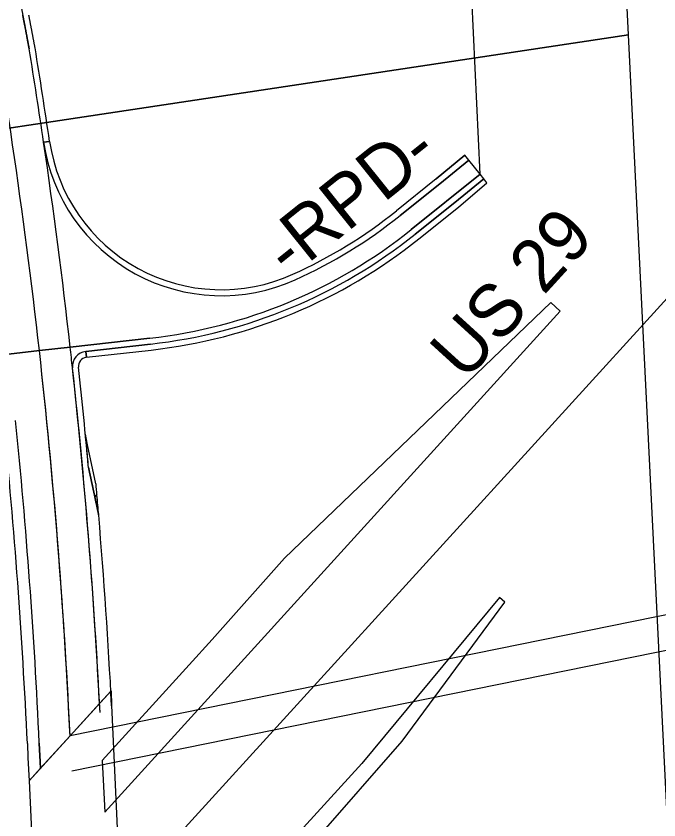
# Model space of a CAD drawing. Extents: x 1805231 to 1809482, y 908883 to 918297.
# Drawn here: x 1807848 to 1808278, y 914790 to 915327 of the extents above; entities that cross this region are included whole.
import ezdxf

# ---------------------------------------------------------------- set-up
doc = ezdxf.new("R2010")
doc.units = 0
for name, color, linetype in [('Old_Level_50', 7, 'Continuous'), ('Prop DSN Text', 7, 'Continuous'), ('Prop Horizontal Alignment', 7, 'Continuous'), ('Prop Horizontal Alignment Station Label', 7, 'Continuous'), ('Prop Shade Medium', 7, 'Continuous')]:
    doc.layers.add(name, color=color, linetype=linetype)

msp = doc.modelspace()

# ---------------------------------------------------------------- linework, layer by layer
at = {"layer": 'Old_Level_50'}
msp.add_lwpolyline([(1807870.06, 914531.76), (1807924.83, 914591.86), (1807911.63, 914876.72), (1807856.86, 914816.62)], close=True, dxfattribs=at)
at = {"layer": 'Prop DSN Text'}
for p, q in [((1807852.79, 915327.36), (1807852.79, 915327.36)), ((1807852.91, 915326.77), (1807852.79, 915327.36)), ((1807856.87, 915305.75), (1807856.77, 915306.3)), ((1807856.93, 915305.41), (1807856.87, 915305.75)), ((1807870.56, 915243.69), (1807866.6, 915243.11)), ((1807870.56, 915243.69), (1807866.6, 915243.11)), ((1807866.6, 915243.11), (1807870.56, 915243.69)), ((1808128.8, 915218.55), (1808148.08, 915234.46)), ((1808148.08, 915234.46), (1808128.8, 915218.55)), ((1808150.74, 915231.15), (1808148.08, 915234.46)), ((1808131.3, 915215.42), (1808150.74, 915231.15)), ((1808150.74, 915231.15), (1808131.3, 915215.42)), ((1808158.31, 915221.69), (1808150.74, 915231.15)), ((1808128.8, 915218.55), (1808102.25, 915197.27)), ((1808112.25, 915184.78), (1808158.31, 915221.69)), ((1808158.31, 915221.69), (1808112.25, 915184.78)), ((1808160.71, 915218.7), (1808141.31, 915202.94)), ((1808141.31, 915202.94), (1808160.71, 915218.7)), ((1808160.71, 915218.7), (1808158.31, 915221.69)), ((1808162.81, 915216.08), (1808160.71, 915218.7)), ((1808104.75, 915194.15), (1808131.3, 915215.42)), ((1808131.3, 915215.42), (1808104.75, 915194.15)), ((1808143.81, 915199.82), (1808162.81, 915216.08)), ((1808141.31, 915202.94), (1808114.75, 915181.66)), ((1808114.75, 915181.66), (1808141.31, 915202.94)), ((1808117.25, 915178.54), (1808143.81, 915199.82)), ((1808205.39, 915135.94), (1808027.54, 914965.21)), ((1808211.73, 915130.28), (1808205.39, 915135.94)), ((1807907.38, 914795.62), (1808211.73, 915130.28)), ((1807884.35, 915106.27), (1807937.6, 915112.25)), ((1807937.6, 915112.25), (1807884.35, 915106.27)), ((1807863.73, 915103.95), (1807884.35, 915106.27)), ((1807884.35, 915106.27), (1807863.73, 915103.95)), ((1807938.05, 915108.27), (1807894.71, 915103.41)), ((1807894.71, 915103.41), (1807938.05, 915108.27)), ((1807843.11, 915101.64), (1807863.73, 915103.95)), ((1807863.73, 915103.95), (1807843.11, 915101.64)), ((1807895.16, 915099.43), (1807894.71, 915103.41)), ((1807894.71, 915103.41), (1807895.16, 915099.43)), ((1807895.16, 915099.43), (1807894.71, 915103.41)), ((1807895.16, 915099.43), (1807938.49, 915104.3)), ((1808931.8, 915059), (1807884.24, 914846.67)), ((1807896.01, 915040.98), (1807894.47, 915048.14)), ((1807896.01, 915040.98), (1807895.19, 915040.72)), ((1807895.19, 915040.72), (1807896.01, 915040.98)), ((1807901.58, 915014.95), (1807896.01, 915040.98)), ((1808787.62, 915005.99), (1807885.34, 914823.11)), ((1808027.54, 914965.21), (1807979.3, 914910.89)), ((1808171.26, 914939.03), (1808079.12, 914828.16)), ((1808174.73, 914935.87), (1808171.26, 914939.03)), ((1807979.3, 914910.89), (1807963.89, 914893.98)), ((1807963.89, 914893.98), (1807905.78, 914830.23)), ((1807884.24, 914846.67), (1807903.94, 914868.28)), ((1807912.04, 914866.67), (1807912.02, 914867.05)), ((1807855.71, 914841.42), (1807856.15, 914831.97)), ((1807864.48, 914824.99), (1807863.7, 914841.79)), ((1807863.7, 914841.79), (1807864.48, 914824.99)), ((1807905.78, 914830.23), (1807907.38, 914795.62)), ((1808079.12, 914828.16), (1807914.26, 914647.28))]:
    msp.add_line(p, q, dxfattribs=at)
for points in [[(1807900.77, 915006.39), (1807901.83, 915007.21), (1807902.24, 915007.53)], [(1807902.24, 915007.53), (1807901.83, 915007.21), (1807900.77, 915006.39)], [(1807984.27, 914696.64), (1808048.82, 914777.64), (1808106.13, 914843.12), (1808174.73, 914935.87)], [(1807904.26, 914862.18), (1807903.94, 914868.28), (1807911.63, 914876.72), (1807912.04, 914866.67)], [(1807864.48, 914824.99), (1807884.24, 914846.67), (1807884.11, 914849.53)], [(1807856.15, 914831.97), (1807856.86, 914816.62), (1807864.48, 914824.99)]]:
    msp.add_lwpolyline(points, dxfattribs=at)
for centre, radius, start, end in [((1803888.72, 914657.58), 4000, 6.4071, 10.37717), ((1803888.72, 914657.58), 4000, 6.4071, 10.37717), ((1803888.72, 914657.58), 4020.75, 8.37352, 9.27189), ((1803888.72, 914657.58), 4020.75, 8.37352, 9.27189), ((1803888.72, 914657.58), 4024.75, 8.37352, 9.27189), ((1807985.32, 915260.58), 120, 188.3735, 294.3215), ((1807985.32, 915260.58), 120, 188.3735, 294.3215), ((1803888.72, 914657.58), 4020.75, 6.4071, 8.37352), ((1803888.72, 914657.58), 4020.75, 6.4071, 8.37352), ((1807985.32, 915260.58), 116, 188.3735, 294.3215), ((1807899.66, 915450.12), 324, 294.3215, 308.7021), ((1807899.66, 915450.12), 328, 294.3215, 308.7021), ((1807899.66, 915450.12), 328, 294.3215, 308.7021), ((1807899.66, 915450.12), 340, 276.4071, 308.7021), ((1807899.66, 915450.12), 340, 276.4071, 308.7021), ((1807899.66, 915450.12), 344, 276.4071, 308.7021), ((1807899.66, 915450.12), 344, 276.4071, 308.7021), ((1807899.66, 915450.12), 348, 276.4071, 308.7021), ((1803888.72, 914657.58), 4020.75, 6.20809, 6.4071), ((1803888.72, 914657.58), 4020.75, 6.20809, 6.4071), ((1803888.72, 914657.58), 4000, 2.75044, 6.4071), ((1803844.06, 914654.02), 4044.77, 2.72997, 6.38663), ((1807895.83, 915093.47), 10, 96.4071, 186.2081), ((1807895.83, 915093.47), 10, 96.4071, 186.2081), ((1807895.83, 915093.47), 6, 96.4071, 186.2081), ((1803888.72, 914657.58), 4020.75, 2.91678, 6.20809), ((1803994.75, 914666.13), 3914.41, 2.96032, 6.25163), ((1803888.72, 914657.58), 4024.75, 5.24815, 6.20809), ((1803888.72, 914657.58), 3979.25, 2.65322, 5.76578), ((1803888.72, 914657.58), 3979.25, 2.65322, 5.76578), ((1803888.72, 914657.58), 3971.25, 2.65322, 5.76578), ((1803888.72, 914657.58), 4024.75, 5.46254, 5.56861), ((1803888.72, 914657.58), 4024.75, 5.24815, 5.46254), ((1803888.72, 914657.58), 4028.75, 4.98316, 5.08905), ((1803888.72, 914657.58), 4028.75, 4.78978, 4.98316), ((1803888.72, 914657.58), 4028.75, 2.98039, 4.78978)]:
    msp.add_arc(centre, radius, start, end, dxfattribs=at)
for points in [[(1807848.53, 915349.29), (1807848.59, 915348.99), (1807848.77, 915348.1), (1807848.94, 915347.22), (1807849.12, 915346.33), (1807849.29, 915345.44), (1807849.47, 915344.55), (1807849.64, 915343.66), (1807849.81, 915342.77), (1807849.99, 915341.88), (1807850.16, 915340.99), (1807850.33, 915340.11), (1807850.51, 915339.22), (1807850.68, 915338.33), (1807850.85, 915337.44), (1807851.02, 915336.55), (1807851.2, 915335.66), (1807851.37, 915334.77), (1807851.54, 915333.88), (1807851.71, 915332.99), (1807851.88, 915332.1), (1807852.05, 915331.21), (1807852.23, 915330.32), (1807852.4, 915329.44), (1807852.57, 915328.55), (1807852.74, 915327.66), (1807852.79, 915327.36)], [(1807852.79, 915327.36), (1807852.91, 915326.77), (1807853.08, 915325.88), (1807853.25, 915324.99), (1807853.42, 915324.1), (1807853.59, 915323.21), (1807853.76, 915322.32), (1807853.93, 915321.43), (1807854.09, 915320.54), (1807854.26, 915319.65), (1807854.43, 915318.76), (1807854.6, 915317.87), (1807854.77, 915316.98), (1807854.94, 915316.09), (1807855.1, 915315.2), (1807855.27, 915314.31), (1807855.44, 915313.42), (1807855.6, 915312.53), (1807855.77, 915311.64), (1807855.94, 915310.75), (1807856.1, 915309.86), (1807856.27, 915308.97), (1807856.44, 915308.08), (1807856.6, 915307.19), (1807856.77, 915306.3), (1807856.93, 915305.41)], [(1807860.88, 915306.05), (1807860.7, 915307.03), (1807860.54, 915307.92), (1807860.37, 915308.81), (1807860.2, 915309.7), (1807860.04, 915310.59), (1807859.87, 915311.48), (1807859.7, 915312.37), (1807859.54, 915313.27), (1807859.37, 915314.16), (1807859.2, 915315.05), (1807859.03, 915315.94), (1807858.87, 915316.83), (1807858.7, 915317.72), (1807858.53, 915318.61), (1807858.36, 915319.5), (1807858.19, 915320.39), (1807858.02, 915321.28), (1807857.85, 915322.17), (1807857.69, 915323.07), (1807857.52, 915323.96), (1807857.35, 915324.85), (1807857.18, 915325.74), (1807857.01, 915326.63), (1807856.84, 915327.52), (1807856.73, 915328.05)], [(1807853.89, 915321.61), (1807853.76, 915322.32), (1807853.62, 915323.04)], [(1807854.78, 915316.89), (1807854.77, 915316.98), (1807854.6, 915317.87), (1807854.43, 915318.76), (1807854.26, 915319.65), (1807854.09, 915320.54), (1807853.93, 915321.43), (1807853.89, 915321.61)], [(1807855.34, 915313.93), (1807855.27, 915314.31), (1807855.1, 915315.2), (1807854.94, 915316.09), (1807854.78, 915316.89)], [(1807898.89, 915015.15), (1807898.83, 915015.44), (1807898.73, 915015.87), (1807898.64, 915016.3), (1807898.55, 915016.73), (1807898.46, 915017.16), (1807898.36, 915017.58), (1807898.27, 915018.01), (1807898.18, 915018.44), (1807898.09, 915018.87), (1807897.99, 915019.3), (1807897.9, 915019.73), (1807897.81, 915020.16), (1807897.71, 915020.58), (1807897.62, 915021.01), (1807897.53, 915021.44), (1807897.43, 915021.87), (1807897.34, 915022.3), (1807897.25, 915022.73), (1807897.15, 915023.16), (1807897.06, 915023.58), (1807896.97, 915024.01), (1807896.87, 915024.44), (1807896.78, 915024.87), (1807896.59, 915025.73)], [(1807896.59, 915025.73), (1807896.78, 915024.87), (1807896.87, 915024.44), (1807896.97, 915024.01), (1807897.06, 915023.58), (1807897.15, 915023.16), (1807897.25, 915022.73), (1807897.34, 915022.3), (1807897.43, 915021.87), (1807897.53, 915021.44), (1807897.62, 915021.01), (1807897.71, 915020.58), (1807897.81, 915020.16), (1807897.9, 915019.73), (1807897.99, 915019.3), (1807898.09, 915018.87), (1807898.18, 915018.44), (1807898.27, 915018.01), (1807898.36, 915017.58), (1807898.46, 915017.16), (1807898.55, 915016.73), (1807898.64, 915016.3), (1807898.73, 915015.87), (1807898.83, 915015.44), (1807898.89, 915015.15)], [(1807901.16, 915004.57), (1807901.13, 915004.72), (1807901.03, 915005.15), (1807900.94, 915005.58), (1807900.85, 915006), (1807900.76, 915006.43), (1807900.67, 915006.86), (1807900.58, 915007.29), (1807900.49, 915007.72), (1807900.39, 915008.15), (1807900.3, 915008.58), (1807900.21, 915009.01), (1807900.12, 915009.44), (1807900.03, 915009.87), (1807899.93, 915010.29), (1807899.84, 915010.72), (1807899.75, 915011.15), (1807899.66, 915011.58), (1807899.57, 915012.01), (1807899.47, 915012.44), (1807899.38, 915012.87), (1807899.29, 915013.3), (1807899.2, 915013.73), (1807899.1, 915014.15), (1807899.01, 915014.58), (1807898.92, 915015.01), (1807898.89, 915015.15)], [(1807898.89, 915015.15), (1807898.92, 915015.01), (1807899.01, 915014.58), (1807899.1, 915014.15), (1807899.2, 915013.73), (1807899.29, 915013.3), (1807899.38, 915012.87), (1807899.47, 915012.44), (1807899.57, 915012.01), (1807899.66, 915011.58), (1807899.75, 915011.15), (1807899.84, 915010.72), (1807899.93, 915010.29), (1807900.03, 915009.87), (1807900.12, 915009.44), (1807900.21, 915009.01), (1807900.3, 915008.58), (1807900.39, 915008.15), (1807900.49, 915007.72), (1807900.58, 915007.29), (1807900.67, 915006.86), (1807900.76, 915006.43), (1807900.77, 915006.39)], [(1807900.77, 915006.39), (1807900.85, 915006), (1807900.94, 915005.58), (1807901.03, 915005.15), (1807901.13, 915004.72), (1807901.16, 915004.57)], [(1807903.4, 914993.98), (1807903.31, 914994.41), (1807903.22, 914994.84), (1807903.13, 914995.27), (1807903.03, 914995.7), (1807902.94, 914996.13), (1807902.85, 914996.56), (1807902.76, 914996.99), (1807902.67, 914997.42), (1807902.58, 914997.85), (1807902.49, 914998.28), (1807902.4, 914998.71), (1807902.31, 914999.14), (1807902.22, 914999.57), (1807902.13, 915000), (1807902.04, 915000.43), (1807901.95, 915000.86), (1807901.86, 915001.28), (1807901.76, 915001.71), (1807901.67, 915002.14), (1807901.58, 915002.57), (1807901.49, 915003), (1807901.4, 915003.43), (1807901.31, 915003.86), (1807901.22, 915004.29), (1807901.16, 915004.57)], [(1807901.16, 915004.57), (1807901.22, 915004.29), (1807901.31, 915003.86), (1807901.4, 915003.43), (1807901.49, 915003), (1807901.58, 915002.57), (1807901.67, 915002.14), (1807901.76, 915001.71), (1807901.86, 915001.28), (1807901.95, 915000.86), (1807902.04, 915000.43), (1807902.13, 915000), (1807902.22, 914999.57), (1807902.31, 914999.14), (1807902.4, 914998.71), (1807902.49, 914998.28), (1807902.58, 914997.85), (1807902.67, 914997.42), (1807902.76, 914996.99), (1807902.85, 914996.56), (1807902.94, 914996.13), (1807903.03, 914995.7), (1807903.13, 914995.27), (1807903.22, 914994.84), (1807903.31, 914994.41), (1807903.4, 914993.98)]]:
    msp.add_spline(points, degree=3, dxfattribs=at)
for points in [[(1807852.79, 915327.36), (1807852.78, 915327.46), (1807852.76, 915327.56), (1807852.74, 915327.66), (1807852.71, 915327.78), (1807852.69, 915327.91), (1807852.67, 915328.03)], [(1807853.08, 915325.88), (1807853.02, 915326.17), (1807852.96, 915326.47), (1807852.91, 915326.77), (1807852.91, 915326.77), (1807852.91, 915326.77), (1807852.91, 915326.77)], [(1807853.3, 915324.73), (1807853.28, 915324.82), (1807853.26, 915324.9), (1807853.25, 915324.99), (1807853.19, 915325.28), (1807853.13, 915325.58), (1807853.08, 915325.88), (1807853.08, 915325.88), (1807853.08, 915325.88), (1807853.08, 915325.88)], [(1807853.62, 915323.04), (1807853.61, 915323.09), (1807853.6, 915323.15), (1807853.59, 915323.21), (1807853.53, 915323.5), (1807853.47, 915323.8), (1807853.42, 915324.1), (1807853.38, 915324.31), (1807853.34, 915324.52), (1807853.3, 915324.73)], [(1807856.16, 915309.57), (1807856.14, 915309.66), (1807856.12, 915309.76), (1807856.1, 915309.86), (1807856.05, 915310.15), (1807855.99, 915310.45), (1807855.94, 915310.75), (1807855.88, 915311.04), (1807855.83, 915311.34), (1807855.77, 915311.64), (1807855.72, 915311.94), (1807855.66, 915312.23), (1807855.6, 915312.53), (1807855.55, 915312.83), (1807855.49, 915313.12), (1807855.44, 915313.42), (1807855.41, 915313.59), (1807855.37, 915313.76), (1807855.34, 915313.93)], [(1807856.77, 915306.3), (1807856.77, 915306.3), (1807856.77, 915306.3), (1807856.77, 915306.3), (1807856.71, 915306.59), (1807856.66, 915306.89), (1807856.6, 915307.19), (1807856.55, 915307.48), (1807856.49, 915307.78), (1807856.44, 915308.08), (1807856.38, 915308.37), (1807856.33, 915308.67), (1807856.27, 915308.97), (1807856.23, 915309.17), (1807856.2, 915309.37), (1807856.16, 915309.57)]]:
    msp.add_open_spline(points, degree=3, dxfattribs=at)
at = {"layer": 'Prop Horizontal Alignment'}
msp.add_line((1807339.38, 914103.38), (1808518.21, 915396.77), dxfattribs=at)
at = {"layer": 'Prop Horizontal Alignment Station Label'}
msp.add_line((1808158.31, 915221.69), (1808146.3, 915469.5), dxfattribs=at)
at = {"layer": 'Prop Shade Medium'}
for points in [[(1808257.25, 915314.81), (1808192.53, 916618.4), (1807143.82, 916566.34), (1807143.82, 916566.34), (1807144.37, 916566.36), (1807218.2, 915068.18), (1807212.6, 915180.97), (1807443.97, 915192.45)], [(1807282.66, 913769.83), (1808331.37, 913821.9), (1808257.25, 915314.81), (1807443.97, 915192.45), (1807212.6, 915180.97), (1807218.2, 915068.18)]]:
    msp.add_lwpolyline(points, close=True, dxfattribs=at)

# ---------------------------------------------------------------- texts
at = {"layer": 'Prop Horizontal Alignment Station Label'}
for s, rotation, p in [('-RPD-', 38.7021, (1808030.77, 915151.9)), ('US 29', 47.6532, (1808148.05, 915082.7))]:
    msp.add_text(s, height=35, rotation=rotation, dxfattribs=at).set_placement(p)

doc.saveas('drawing.dxf')
